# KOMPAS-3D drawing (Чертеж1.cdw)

Referenced files in H:\Users\коша\Desktop\: Чертеж1.cdw
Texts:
  коша
  133 1 134 1 135 1 136 0 50 1|SPDS|133 1 134 1 135 1 136 0 50 1
  125 1 126 1 127 1 128 0 50 1|SPDS|125 1 126 1 127 1 128 0 50 1
  129 1 130 1 131 1 132 0 50 1|SPDS|129 1 130 1 131 1 132 0 50 1
  Титановая губка
  загрязнённая
  примесями
  Пары TiCl4
  Подача TiCl4
  Движение MgCl2
  MgCl2
  Начальный
  уровень Mg
  Основное движение Mg
  Движение Mg
  Стили документа
Dimensions and other numbers on the sheet: 1:1; 1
